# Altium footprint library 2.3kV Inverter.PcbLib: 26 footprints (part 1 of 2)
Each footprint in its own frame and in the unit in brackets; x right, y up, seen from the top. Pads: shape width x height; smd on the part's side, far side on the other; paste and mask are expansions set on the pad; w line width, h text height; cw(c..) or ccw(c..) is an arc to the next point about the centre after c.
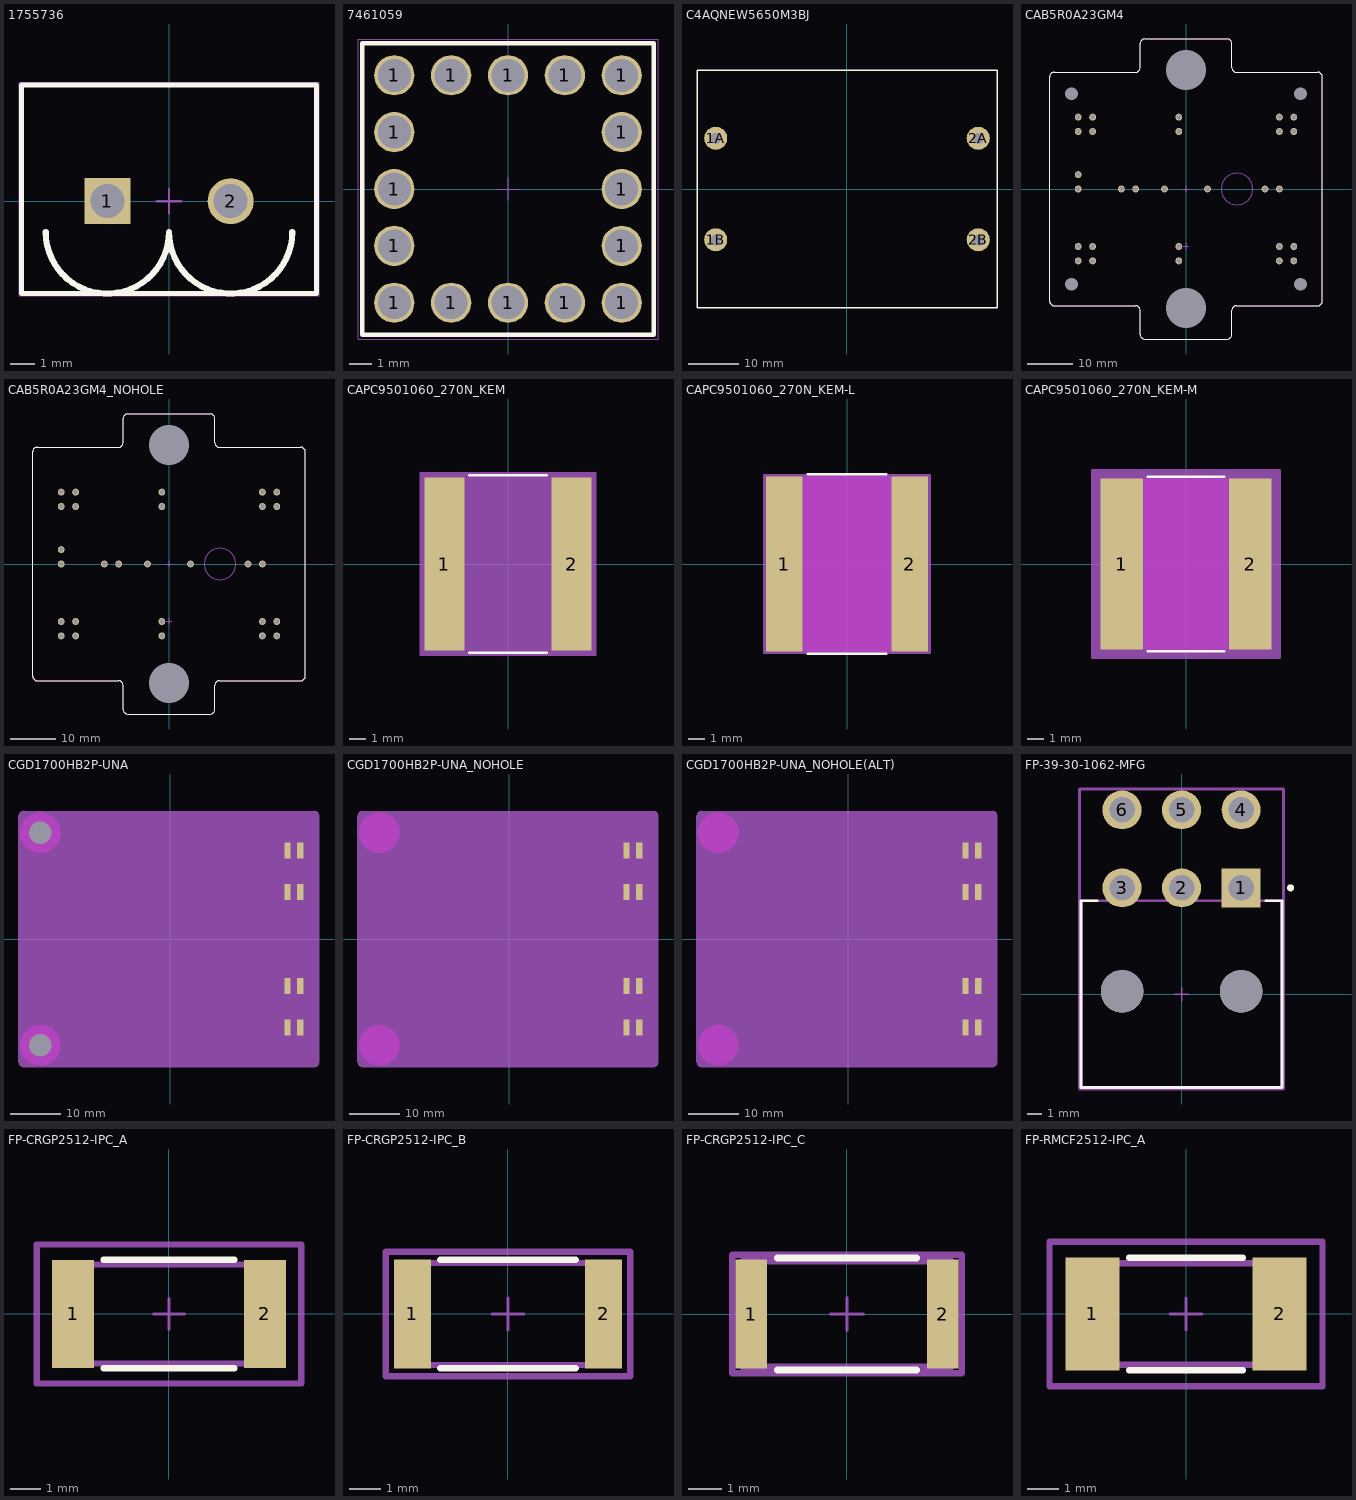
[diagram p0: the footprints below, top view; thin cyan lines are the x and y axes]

## 1755736 [mm] "THD, 2-Leads, Body 12.16x8.6mm, Pitch 5.08mm"
height 12
pads (2):
  rect 1.9x1.9 hole 1.4: 1(-2.54,0)
  round 1.9 hole 1.4: 2(2.54,0)
Top Overlay:
  lines w0.2: -6.08,-3.81 -6.08,4.79 6.08,4.79 6.08,-3.81 -6.08,-3.81
  lines w0.254: -5.08,-1.27 ccw(c-2.54,-1.27) 0,-1.27 ccw(c2.54,-1.27) 5.08,-1.27
Mechanical 13:
  lines w0.1: -6.08,-3.8 6.08,-3.8 6.08,4.8 -6.08,4.8 -6.08,-3.8
Mechanical 15:
  lines w0.05: -6.18,-3.9 -6.18,4.9 6.18,4.9 6.18,-3.9 -6.18,-3.9
  lines w0.1: -0.5,0 0.5,0 ; 0,-0.5 0,0.5
3D body: height 10, standoff -3.9, extent -3.04,-0.499 -2.044,0.499
3D body: height 10, standoff -3.9, extent 2.04,-0.499 3.036,0.499
3D body: height 12, standoff 4, extent -6.079,-3.799 6.079,4.799
3D body "Phoenix Contact 1755736.stp": height 12, standoff -3.9, extent -6,-3.7 6.16,4.87

## 7461059 [mm] "M6, thr 13.5mm"
height 13.5
pads (16):
  round 1.8 hole 1.475: 1(-5.08,-5.08) 1(-5.08,-2.54) 1(-5.08,0) 1(-5.08,2.54) 1(-5.08,5.08) 1(-2.54,-5.08) 1(-2.54,5.08) 1(0,-5.08) 1(0,5.08) 1(2.54,-5.08) 1(2.54,5.08) 1(5.08,-5.08) 1(5.08,-2.54) 1(5.08,0) 1(5.08,2.54) 1(5.08,5.08)
Top Overlay:
  lines w0.2: -6.5,-6.5 -6.5,6.5 6.5,6.5 6.5,-6.5 -6.5,-6.5
Top Courtyard:
  lines w0.05: -0.5,0 0.5,0 ; 0,-0.5 0,0.5 ; -6.7,-6.7 -6.7,6.7 6.7,6.7 6.7,-6.7 -6.7,-6.7
Top 3D Body:
  lines w0.1: -6.5,-6.5 -6.5,6.5 6.5,6.5 6.5,-6.5 -6.5,-6.5
Top Component Outline:
  lines w0.1: -6.5,-6.5 6.5,-6.5 6.5,6.5 -6.5,6.5 -6.5,-6.5
Top Designator:
  text ".Designator" at -7.498,-0.5 h1.5
3D body "7461059.STEP": height 13.5, standoff -3.5, extent -6.5,-6.5 6.5,6.5

## C4AQNEW5650M3BJ [mm]
pads (4):
  round 4.6 hole 2.2: 1A(-26.25,10.15) 1B(-26.25,-10.15) 2A(26.25,10.15) 2B(26.25,-10.15)
Top Overlay:
  lines w0.254: -30,-23.75 -30,23.75 30,23.75 30,-23.75 -30,-23.75
3D body "C4AQNEW5650M3BJ.step": height 65.3, standoff -6, extent -29.15,-22.805 29.15,22.7

## CAB5R0A23GM4 [mm] "Wolfpack GM Half-Bridge 2.3kV footprint"
pads (34):
  round 1.524 hole 1.1: AC_1(-24,-12.8) AC_2(-24,-16) AC_3(-20.8,-12.8) AC_4(-20.8,-16) AC_5(20.8,-12.8) AC_6(20.8,-16) AC_7(24,-12.8) AC_8(24,-16) DC+_1(-24,16) DC+_2(-24,12.8) DC+_3(-20.8,16) DC+_4(-20.8,12.8) DC+_5(20.8,16) DC+_6(20.8,12.8) DC+_7(24,16) DC+_8(24,12.8) DC-_1(20.8,0) DC-_2(17.6,0) DC-_3(-4.8,0) DC-_4(4.8,0) DC-_5(-11.2,0) DC-_6(-14.4,0) G1(-1.6,16) G2(-1.6,-16) S1(-1.6,12.8) S2(-1.6,-12.8) T1(-24,3.2) T2(-24,0)
  round 0.099 / inner round 1.524 / far side round 0.099 hole 2.794 unplated: ""(-25.5,-21.25) ""(-25.5,21.25) ""(25.5,-21.25) ""(25.5,21.25)
  round 0.1 hole 9 unplated: ""(0,-26.5) ""(0,26.5)
Top Overlay:
  lines w0.254: -30.35,-25 ccw(c-29.35,-25) -29.35,-26 -11.2,-26 cw(c-11.2,-27) -10.2,-27 -10.2,-32.4 ccw(c-9.2,-32.4) -9.2,-33.4 9.2,-33.4 ccw(c9.2,-32.4) 10.2,-32.4 10.2,-27 cw(c11.2,-27) 11.2,-26 29.35,-26 ccw(c29.35,-25) 30.35,-25 30.35,25 ccw(c29.35,25) 29.35,26 11.2,26 cw(c11.2,27) 10.2,27 10.2,32.4 ccw(c9.2,32.4) 9.2,33.4 -9.2,33.4 ccw(c-9.2,32.4) -10.2,32.4 -10.2,27 cw(c-11.2,27) -11.2,26 -29.35,26 ccw(c-29.35,25) -30.35,25 -30.35,-25
Mechanical 1:
  text "Hole size and tolerance need to checked before using this footprint" at 26,34.5 h1.52
  text "This footprint is mirrored. The footprint can be used on the bottom PCB side for module attach" at 23.5,-42.5 h1.52
Mechanical 5:
  text "G2" at 3.54,-16.46 h0.64
  text "AC_1" at -27.96,-13.248 h0.64
  text "T2" at 26.04,-0.46 h0.64
  text "T1" at 26.04,3.04 h0.64
  text "DC-_1" at -22.46,2.252 h0.64
  text "S1" at -0.96,12.54 h0.64
  text "T1" at -21.96,11.54 h0.64
  text "G1" at -0.96,15.54 h0.64
  text "DC+_1" at -28.46,15.752 h0.64
  text "T1" at -21.96,15.04 h0.64
  text "T2" at -21.96,12.04 h0.64
  text "DC+_2" at -28.46,12.452 h0.64
  text "DC+_3" at -18.96,15.752 h0.64
  text "DC+_4" at -18.96,12.452 h0.64
  text "DC+_5" at 16.04,15.752 h0.64
  text "DC+_6" at 16.04,12.452 h0.64
  text "DC+_7" at 26.04,15.752 h0.64
  text "DC+_8" at 26.04,12.452 h0.64
  text "DC-_2" at -18.96,2.252 h0.64
  text "DC-_3" at -6.46,2.252 h0.64
  text "DC-_4" at 3.54,2.252 h0.64
  text "DC-_5" at 9.54,2.252 h0.64
  text "DC-_6" at 13.04,2.252 h0.64
  text "S2" at 3.54,-13.16 h0.64
  text "AC_2" at -27.96,-16.248 h0.64
  text "AC_3" at -18.96,-13.248 h0.64
  text "AC_4" at -18.96,-16.248 h0.64
  text "AC_5" at 16.54,-13.248 h0.64
  text "AC_6" at 16.54,-16.248 h0.64
  text "AC_7" at 26.04,-13.248 h0.64
  text "AC_8" at 26.04,-16.248 h0.64
Mechanical 6:
  circle w0.25: c11.35,0 r3.5
  lines w0.254: -30.35,-25 ccw(c-29.35,-25) -29.35,-26 -11.2,-26 cw(c-11.2,-27) -10.2,-27 -10.2,-32.4 ccw(c-9.2,-32.4) -9.2,-33.4 9.2,-33.4 ccw(c9.2,-32.4) 10.2,-32.4 10.2,-27 cw(c11.2,-27) 11.2,-26 29.35,-26 ccw(c29.35,-25) 30.35,-25 30.35,25 ccw(c29.35,25) 29.35,26 11.2,26 cw(c11.2,27) 10.2,27 10.2,32.4 ccw(c9.2,32.4) 9.2,33.4 -9.2,33.4 ccw(c-9.2,32.4) -10.2,32.4 -10.2,27 cw(c-11.2,27) -11.2,26 -29.35,26 ccw(c-29.35,25) -30.35,25 -30.35,-25
Mechanical 8:
  lines w0.25: -0.67,-12.8 0.635,-12.8 ; -0.67,0 0.635,0 ; 0,-13.435 0,-12.13 ; 0,-0.635 0,0.67
3D body "CABxRxA23GM4.STEP": height 14.24, standoff -2.16, extent -28.346,-31.391 28.354,31.409

## CAB5R0A23GM4_NOHOLE [mm] "Wolfpack GM Half-Bridge 2.3kV footprint"
pads (30):
  round 1.524 hole 1.1: AC_1(-24,-12.8) AC_2(-24,-16) AC_3(-20.8,-12.8) AC_4(-20.8,-16) AC_5(20.8,-12.8) AC_6(20.8,-16) AC_7(24,-12.8) AC_8(24,-16) DC+_1(-24,16) DC+_2(-24,12.8) DC+_3(-20.8,16) DC+_4(-20.8,12.8) DC+_5(20.8,16) DC+_6(20.8,12.8) DC+_7(24,16) DC+_8(24,12.8) DC-_1(20.8,0) DC-_2(17.6,0) DC-_3(-4.8,0) DC-_4(4.8,0) DC-_5(-11.2,0) DC-_6(-14.4,0) G1(-1.6,16) G2(-1.6,-16) S1(-1.6,12.8) S2(-1.6,-12.8) T1(-24,3.2) T2(-24,0)
  round 0.1 hole 9 unplated: ""(0,-26.5) ""(0,26.5)
Top Overlay:
  lines w0.254: -30.35,-25 ccw(c-29.35,-25) -29.35,-26 -11.2,-26 cw(c-11.2,-27) -10.2,-27 -10.2,-32.4 ccw(c-9.2,-32.4) -9.2,-33.4 9.2,-33.4 ccw(c9.2,-32.4) 10.2,-32.4 10.2,-27 cw(c11.2,-27) 11.2,-26 29.35,-26 ccw(c29.35,-25) 30.35,-25 30.35,25 ccw(c29.35,25) 29.35,26 11.2,26 cw(c11.2,27) 10.2,27 10.2,32.4 ccw(c9.2,32.4) 9.2,33.4 -9.2,33.4 ccw(c-9.2,32.4) -10.2,32.4 -10.2,27 cw(c-11.2,27) -11.2,26 -29.35,26 ccw(c-29.35,25) -30.35,25 -30.35,-25
Mechanical 1:
  text "Hole size and tolerance need to checked before using this footprint" at 26,34.5 h1.52
  text "This footprint is mirrored. The footprint can be used on the bottom PCB side for module attach" at 23.5,-42.5 h1.52
Mechanical 5:
  text "G2" at 3.54,-16.46 h0.64
  text "AC_1" at -27.96,-13.248 h0.64
  text "T2" at 26.04,-0.46 h0.64
  text "T1" at 26.04,3.04 h0.64
  text "DC-_1" at -22.46,2.252 h0.64
  text "S1" at -0.96,12.54 h0.64
  text "T1" at -21.96,11.54 h0.64
  text "G1" at -0.96,15.54 h0.64
  text "DC+_1" at -28.46,15.752 h0.64
  text "T1" at -21.96,15.04 h0.64
  text "T2" at -21.96,12.04 h0.64
  text "DC+_2" at -28.46,12.452 h0.64
  text "DC+_3" at -18.96,15.752 h0.64
  text "DC+_4" at -18.96,12.452 h0.64
  text "DC+_5" at 16.04,15.752 h0.64
  text "DC+_6" at 16.04,12.452 h0.64
  text "DC+_7" at 26.04,15.752 h0.64
  text "DC+_8" at 26.04,12.452 h0.64
  text "DC-_2" at -18.96,2.252 h0.64
  text "DC-_3" at -6.46,2.252 h0.64
  text "DC-_4" at 3.54,2.252 h0.64
  text "DC-_5" at 9.54,2.252 h0.64
  text "DC-_6" at 13.04,2.252 h0.64
  text "S2" at 3.54,-13.16 h0.64
  text "AC_2" at -27.96,-16.248 h0.64
  text "AC_3" at -18.96,-13.248 h0.64
  text "AC_4" at -18.96,-16.248 h0.64
  text "AC_5" at 16.54,-13.248 h0.64
  text "AC_6" at 16.54,-16.248 h0.64
  text "AC_7" at 26.04,-13.248 h0.64
  text "AC_8" at 26.04,-16.248 h0.64
Mechanical 6:
  circle w0.25: c11.35,0 r3.5
  lines w0.254: -30.35,-25 ccw(c-29.35,-25) -29.35,-26 -11.2,-26 cw(c-11.2,-27) -10.2,-27 -10.2,-32.4 ccw(c-9.2,-32.4) -9.2,-33.4 9.2,-33.4 ccw(c9.2,-32.4) 10.2,-32.4 10.2,-27 cw(c11.2,-27) 11.2,-26 29.35,-26 ccw(c29.35,-25) 30.35,-25 30.35,25 ccw(c29.35,25) 29.35,26 11.2,26 cw(c11.2,27) 10.2,27 10.2,32.4 ccw(c9.2,32.4) 9.2,33.4 -9.2,33.4 ccw(c-9.2,32.4) -10.2,32.4 -10.2,27 cw(c-11.2,27) -11.2,26 -29.35,26 ccw(c-29.35,25) -30.35,25 -30.35,-25
Mechanical 8:
  lines w0.25: -0.67,-12.8 0.635,-12.8 ; -0.67,0 0.635,0 ; 0,-13.435 0,-12.13 ; 0,-0.635 0,0.67
3D body "93070A095_Alloy Steel Low-Profile Socket Head Screw.STEP": height 17.35, standoff 8.55, extent -3.488,23 3.488,30
3D body "93070A095_Alloy Steel Low-Profile Socket Head Screw.STEP": height 17.35, standoff 8.55, extent -3.488,-30 3.488,-23
3D body "CABxRxA23GM4.STEP": height 14.24, standoff -2.16, extent -28.346,-31.391 28.354,31.409

## CAPC9501060_270N_KEM [mm]
pads (2):
  rect 2.426x10.6 smd paste+0 mask+0: 1(-3.893,0) 2(3.893,0)
Top Overlay:
  lines w0.152: -2.372,-5.427 2.372,-5.427 ; -2.372,5.427 2.372,5.427
Top Solder:
  rectangle: -2.73,-5.524 2.73,5.524
Mechanical 13:
  lines w0.025: -4.75,-5.3 -4.75,5.3 ; -4.75,-5.3 4.75,-5.3 ; -4.75,-5.3 -3.08,-5.3 -3.08,5.3 -4.75,5.3 ; -4.75,-5.3 -4.75,5.3 ; -4.75,5.3 4.75,5.3 ; 4.75,-5.3 4.75,5.3 ; 4.75,-5.3 4.75,5.3 ; 4.75,-5.3 3.08,-5.3 3.08,5.3 4.75,5.3
Mechanical 15:
  region: 5.36,-5.554 -5.36,-5.554 -5.36,5.554 5.36,5.554
  lines w0.152: -5.36,-5.554 5.36,-5.554 5.36,5.554 -5.36,5.554 -5.36,-5.554
3D body "CAPC9501060_270N_KEM.step": height 2.7, standoff 0, extent -4.75,-5.3 4.75,5.3

## CAPC9501060_270N_KEM-L [mm]
pads (2):
  rect 2.222x10.549 smd paste+0 mask+0: 1(-3.791,0) 2(3.791,0)
Top Layer keep-out:
  region: -2.629,-5.249 -2.629,5.249 2.629,5.249 2.629,-5.249
Top Overlay:
  lines w0.152: -2.384,-5.427 2.384,-5.427 ; -2.384,5.427 2.384,5.427
Keep-Out Layer:
  region: -2.629,-5.3 -2.629,5.3 2.629,5.3 2.629,-5.3
Mechanical 13:
  lines w0.025: -4.75,-5.3 -4.75,5.3 ; -4.75,-5.3 4.75,-5.3 ; -4.75,-5.3 -3.08,-5.3 -3.08,5.3 -4.75,5.3 ; -4.75,-5.3 -4.75,5.3 ; -4.75,5.3 4.75,5.3 ; 4.75,-5.3 4.75,5.3 ; 4.75,-5.3 4.75,5.3 ; 4.75,-5.3 3.08,-5.3 3.08,5.3 4.75,5.3
Mechanical 15:
  region: 5.004,-5.376 -5.004,-5.376 -5.004,5.376 5.004,5.376
  lines w0.152: -5.004,-5.376 5.004,-5.376 5.004,5.376 -5.004,5.376 -5.004,-5.376
3D body "CAPC9501060_270N_KEM.step": height 2.7, standoff 0, extent -4.75,-5.3 4.75,5.3

## CAPC9501060_270N_KEM-M [mm]
pads (2):
  rect 2.629x10.651 smd paste+0 mask+0: 1(-3.994,0) 2(3.994,0)
Top Layer keep-out:
  region: -2.629,-5.249 -2.629,5.249 2.629,5.249 2.629,-5.249
Top Overlay:
  lines w0.152: -2.363,-5.427 2.363,-5.427 ; -2.363,5.427 2.363,5.427
Keep-Out Layer:
  region: -2.629,-5.3 -2.629,5.3 2.629,5.3 2.629,-5.3
Mechanical 13:
  lines w0.025: -4.75,-5.3 -4.75,5.3 ; -4.75,-5.3 4.75,-5.3 ; -4.75,-5.3 -3.08,-5.3 -3.08,5.3 -4.75,5.3 ; -4.75,-5.3 -4.75,5.3 ; -4.75,5.3 4.75,5.3 ; 4.75,-5.3 4.75,5.3 ; 4.75,-5.3 4.75,5.3 ; 4.75,-5.3 3.08,-5.3 3.08,5.3 4.75,5.3
Mechanical 15:
  region: 5.817,-5.833 -5.817,-5.833 -5.817,5.833 5.817,5.833
  lines w0.152: -5.817,-5.833 5.817,-5.833 5.817,5.833 -5.817,5.833 -5.817,-5.833
3D body "CAPC9501060_270N_KEM.step": height 2.7, standoff 0, extent -4.75,-5.3 4.75,5.3

## CGD1700HB2P-UNA [mil] "Wolfpack FM/GM Gate Driver"
pads (10):
  rect 50x125 smd: 1A(917.84,369) 1B(917.84,-694) 2A(917.84,694) 2B(917.84,-369) 3A(1017.84,369) 3B(1017.84,-694) 4A(1017.84,694) 4B(1017.84,-369)
  round 20 hole 175 unplated: ""(-1017.84,-832.52) ""(-1017.84,832.52)
Top Courtyard:
  dashed: 1164.68,-965 1164.68,965 1164.55,968.05 1164.15,971.08 1163.49,974.06 1162.57,976.97 1161.41,979.79 1160,982.5 1158.36,985.08 1156.5,987.5 1154.43,989.75 1152.18,991.81 1149.76,993.67 1147.18,995.31 1144.48,996.72 1141.66,997.89 1138.74,998.81 1135.76,999.47 1132.74,999.87 1129.68,1000 -1150.32,1000 -1153.37,999.87 -1156.39,999.47 -1159.37,998.81 -1162.29,997.89 -1165.11,996.72 -1167.82,995.31 -1170.39,993.67 -1172.81,991.81 -1175.06,989.75 -1177.13,987.5 -1178.99,985.08 -1180.63,982.5 -1182.04,979.79 -1183.2,976.97 -1184.12,974.06 -1184.78,971.08 -1185.18,968.05 -1185.32,965 -1185.32,-965 -1185.18,-968.05 -1184.78,-971.08 -1184.12,-974.06 -1183.2,-976.97 -1182.04,-979.79 -1180.63,-982.5 -1178.99,-985.08 -1177.13,-987.5 -1175.06,-989.75 -1172.81,-991.81 -1170.39,-993.67 -1167.82,-995.31 -1165.11,-996.72 -1162.29,-997.89 -1159.37,-998.81 -1156.39,-999.47 -1153.37,-999.87 -1150.32,-1000 1129.68,-1000 1132.74,-999.87 1135.76,-999.47 1138.74,-998.81 1141.66,-997.89 1144.48,-996.72 1147.18,-995.31 1149.76,-993.67 1152.18,-991.81 1154.43,-989.75 1156.5,-987.5 1158.36,-985.08 1160,-982.5 1161.41,-979.79 1162.57,-976.97 1163.49,-974.06 1164.15,-971.08 1164.55,-968.05
Top 3D Body:
  region: 1164.68,-965 1164.68,965 1164.55,968.05 1164.15,971.08 1163.49,974.06 1162.57,976.97 1161.41,979.79 1160,982.5 1158.36,985.08 1156.5,987.5 1154.43,989.75 1152.18,991.81 1149.76,993.67 1147.18,995.31 1144.48,996.72 1141.66,997.89 1138.74,998.81 1135.76,999.47 1132.74,999.87 1129.68,1000 -1150.32,1000 -1153.37,999.87 -1156.39,999.47 -1159.37,998.81 -1162.29,997.89 -1165.11,996.72 -1167.82,995.31 -1170.39,993.67 -1172.81,991.81 -1175.06,989.75 -1177.13,987.5 -1178.99,985.08 -1180.63,982.5 -1182.04,979.79 -1183.2,976.97 -1184.12,974.06 -1184.78,971.08 -1185.18,968.05 -1185.32,965 -1185.32,-965 -1185.18,-968.05 -1184.78,-971.08 -1184.12,-974.06 -1183.2,-976.97 -1182.04,-979.79 -1180.63,-982.5 -1178.99,-985.08 -1177.13,-987.5 -1175.06,-989.75 -1172.81,-991.81 -1170.39,-993.67 -1167.82,-995.31 -1165.11,-996.72 -1162.29,-997.89 -1159.37,-998.81 -1156.39,-999.47 -1153.37,-999.87 -1150.32,-1000 1129.68,-1000 1132.74,-999.87 1135.76,-999.47 1138.74,-998.81 1141.66,-997.89 1144.48,-996.72 1147.18,-995.31 1149.76,-993.67 1152.18,-991.81 1154.43,-989.75 1156.5,-987.5 1158.36,-985.08 1160,-982.5 1161.41,-979.79 1162.57,-976.97 1163.49,-974.06 1164.15,-971.08 1164.55,-968.05
Mechanical 12:
  lines w1: 867.84,-631.5 867.84,-431.5 1067.84,-431.5 1067.84,-631.5 867.84,-631.5 ; 867.84,431.5 867.84,631.5 1067.84,631.5 1067.84,431.5 867.84,431.5 ; 917.83,-611.5 cw(c917.83,-581.5) 917.83,-551.49 cw(c917.83,-581.5) 917.83,-611.5 ; 917.83,-511.5 cw(c917.83,-481.5) 917.83,-451.49 cw(c917.83,-481.5) 917.83,-511.5 ; 917.83,451.49 cw(c917.83,481.5) 917.83,511.5 cw(c917.83,481.5) 917.83,451.49 ; 917.83,551.49 cw(c917.83,581.5) 917.83,611.5 cw(c917.83,581.5) 917.83,551.49 ; 1017.83,-611.5 cw(c1017.83,-581.5) 1017.83,-551.49 cw(c1017.83,-581.5) 1017.83,-611.5 ; 1017.83,-511.5 cw(c1017.83,-481.5) 1017.83,-451.49 cw(c1017.83,-481.5) 1017.83,-511.5 ; 1017.83,451.49 cw(c1017.83,481.5) 1017.83,511.5 cw(c1017.83,481.5) 1017.83,451.49 ; 1017.83,551.49 cw(c1017.83,581.5) 1017.83,611.5 cw(c1017.83,581.5) 1017.83,551.49
Mechanical 13:
  lines w1: 892.84,-619 1042.84,-619 1042.84,-444 892.84,-444 892.84,-619 ; 892.84,444 1042.84,444 1042.84,619 892.84,619 892.84,444
Mechanical 15:
  text "4" at 997.84,-744 h25
  text "42" at 877.84,-744 h25
  text "2" at 997.84,319 h25
  text "22" at 877.84,319 h25
  text "3" at 997.84,-419 h25
  text "32" at 877.84,-419 h25
  text "1" at 997.84,644 h25
  text "12" at 877.84,644 h25
Top Assembly:
  circle w1: c-1017.84,832.52 r87.5
  circle w1: c-1017.84,-832.52 r87.5
  lines w1: -1185.32,-965 ccw(c-1150.32,-965) -1150.32,-1000 1129.68,-1000 ccw(c1129.68,-965) 1164.68,-965 1164.68,965 ccw(c1129.68,965) 1129.68,1000 -1150.32,1000 ccw(c-1150.32,965) -1185.32,965 -1185.32,-965 ; -1175.32,-550 -815.32,-550 -815.32,550 -1175.32,550 -1175.32,-550 ; -1175.32,-95 -1135.32,-95 -1135.32,95 -1175.32,95 -1175.32,-95 ; -1045.32,-370 cw(c-1045.32,-350) -1045.32,-330 cw(c-1045.32,-350) -1045.32,-370 ; -1045.32,-270 cw(c-1045.32,-250) -1045.32,-230 cw(c-1045.32,-250) -1045.32,-270 ; -1045.32,-170 cw(c-1045.32,-150) -1045.32,-130 cw(c-1045.32,-150) -1045.32,-170 ; -1045.32,-70 cw(c-1045.32,-50) -1045.32,-30 cw(c-1045.32,-50) -1045.32,-70 ; -1045.32,30 cw(c-1045.32,50) -1045.32,70 cw(c-1045.32,50) -1045.32,30 ; -1045.32,130 cw(c-1045.32,150) -1045.32,170 cw(c-1045.32,150) -1045.32,130 ; -1045.32,230 cw(c-1045.32,250) -1045.32,270 cw(c-1045.32,250) -1045.32,230 ; -1045.32,330 cw(c-1045.32,350) -1045.32,370 cw(c-1045.32,350) -1045.32,330 ; -945.32,-370 cw(c-945.32,-350) -945.32,-330 cw(c-945.32,-350) -945.32,-370 ; -945.32,-270 cw(c-945.32,-250) -945.32,-230 cw(c-945.32,-250) -945.32,-270 ; -945.32,-170 cw(c-945.32,-150) -945.32,-130 cw(c-945.32,-150) -945.32,-170 ; -945.32,-70 cw(c-945.32,-50) -945.32,-30 cw(c-945.32,-50) -945.32,-70 ; -945.32,30 cw(c-945.32,50) -945.32,70 cw(c-945.32,50) -945.32,30 ; -945.32,130 cw(c-945.32,150) -945.32,170 cw(c-945.32,150) -945.32,130 ; -945.32,230 cw(c-945.32,250) -945.32,270 cw(c-945.32,250) -945.32,230 ; -945.32,330 cw(c-945.32,350) -945.32,370 cw(c-945.32,350) -945.32,330 ; 867.84,-631.5 1067.84,-631.5 1067.84,-431.5 867.84,-431.5 867.84,-631.5 ; 867.84,431.5 1067.84,431.5 1067.84,631.5 867.84,631.5 867.84,431.5
  text "HS" at 1155.18,470.79 h75
  text "LS" at 1155.18,-589.21 h75
  text "S" at 1002.18,247 h75
  text "G" at 1002.18,772 h75
  text "G" at 1002.18,-303 h75
  text "S" at 1002.18,-828 h75
Multi-Layer keep-out:
  region: -1017.84,-675.04 -1031.56,-675.64 -1045.18,-677.43 -1058.59,-680.41 -1071.7,-684.54 -1084.39,-689.79 -1096.58,-696.14 -1108.16,-703.52 -1119.06,-711.88 -1129.19,-721.16 -1138.47,-731.29 -1146.84,-742.19 -1154.22,-753.78 -1160.56,-765.97 -1165.82,-778.66 -1169.95,-791.76 -1172.92,-805.17 -1174.72,-818.79 -1175.32,-832.52 -1174.72,-846.25 -1172.92,-859.87 -1169.95,-873.28 -1165.82,-886.38 -1160.56,-899.07 -1154.22,-911.26 -1146.84,-922.85 -1138.47,-933.75 -1129.19,-943.88 -1119.06,-953.16 -1108.16,-961.52 -1096.58,-968.9 -1084.39,-975.25 -1071.7,-980.5 -1058.59,-984.63 -1045.18,-987.61 -1031.56,-989.4 -1017.84,-990 -1004.11,-989.4 -990.49,-987.61 -977.08,-984.63 -963.97,-980.5 -951.28,-975.25 -939.1,-968.9 -927.51,-961.52 -916.61,-953.16 -906.48,-943.88 -897.2,-933.75 -888.83,-922.85 -881.45,-911.26 -875.11,-899.07 -869.85,-886.38 -865.72,-873.28 -862.75,-859.87 -860.95,-846.25 -860.36,-832.52 -860.95,-818.79 -862.75,-805.17 -865.72,-791.76 -869.85,-778.66 -875.11,-765.97 -881.45,-753.78 -888.83,-742.19 -897.2,-731.29 -906.48,-721.16 -916.61,-711.88 -927.51,-703.52 -939.1,-696.14 -951.28,-689.79 -963.97,-684.54 -977.08,-680.41 -990.49,-677.43 -1004.11,-675.64
  region: -1017.84,990 -1031.56,989.4 -1045.18,987.61 -1058.59,984.63 -1071.7,980.5 -1084.39,975.25 -1096.58,968.9 -1108.16,961.52 -1119.06,953.16 -1129.19,943.88 -1138.47,933.75 -1146.84,922.85 -1154.22,911.26 -1160.56,899.07 -1165.82,886.38 -1169.95,873.28 -1172.92,859.87 -1174.72,846.25 -1175.32,832.52 -1174.72,818.79 -1172.92,805.17 -1169.95,791.76 -1165.82,778.66 -1160.56,765.97 -1154.22,753.78 -1146.84,742.19 -1138.47,731.29 -1129.19,721.16 -1119.06,711.88 -1108.16,703.52 -1096.58,696.14 -1084.39,689.79 -1071.7,684.54 -1058.59,680.41 -1045.18,677.43 -1031.56,675.64 -1017.84,675.04 -1004.11,675.64 -990.49,677.43 -977.08,680.41 -963.97,684.54 -951.28,689.79 -939.1,696.14 -927.51,703.52 -916.61,711.88 -906.48,721.16 -897.2,731.29 -888.83,742.19 -881.45,753.78 -875.11,765.97 -869.85,778.66 -865.72,791.76 -862.75,805.17 -860.95,818.79 -860.36,832.52 -860.95,846.25 -862.75,859.87 -865.72,873.28 -869.85,886.38 -875.11,899.07 -881.45,911.26 -888.83,922.85 -897.2,933.75 -906.48,943.88 -916.61,953.16 -927.51,961.52 -939.1,968.9 -951.28,975.25 -963.97,980.5 -977.08,984.63 -990.49,987.61 -1004.11,989.4
Mechanical 17:
  lines w1: -1185.32,-965 ccw(c-1150.32,-965) -1150.32,-1000 1129.68,-1000 ccw(c1129.68,-965) 1164.68,-965 1164.68,965 ccw(c1129.68,965) 1129.68,1000 -1150.32,1000 ccw(c-1150.32,965) -1185.32,965 -1185.32,-965
3D body "CGD1700HB2M-UNA STEP.STEP": height 1020.55, standoff 158.13, extent -1185,-1237 1165,1000
3D body "TSM-102-01-SM-DV.step": height 390, standoff 0, extent 870,-681.5 1070,-378.5
3D body "TSM-102-01-SM-DV.step": height 390, standoff 0, extent 865,378.5 1065,681.5
3D body "95783A015_Nylon 6-6 Male-Female Threaded Hex Standoff.STEP": height 846.46, standoff 0, extent -1135.95,-965.19 -899.72,-699.85
3D body "95783A015_Nylon 6-6 Male-Female Threaded Hex Standoff.STEP": height 846.46, standoff 0, extent -1135.95,699.85 -899.72,965.19

## CGD1700HB2P-UNA_NOHOLE [mil] "Wolfpack FM/GM Gate Driver"
pads (8):
  rect 50x125 smd: 1A(917.84,369) 1B(917.84,-694) 2A(917.84,694) 2B(917.84,-369) 3A(1017.84,369) 3B(1017.84,-694) 4A(1017.84,694) 4B(1017.84,-369)
Top Courtyard:
  dashed: 1164.68,-965 1164.68,965 1164.55,968.05 1164.15,971.08 1163.49,974.06 1162.57,976.97 1161.41,979.79 1160,982.5 1158.36,985.08 1156.5,987.5 1154.43,989.75 1152.18,991.81 1149.76,993.67 1147.18,995.31 1144.48,996.72 1141.66,997.89 1138.74,998.81 1135.76,999.47 1132.74,999.87 1129.68,1000 -1150.32,1000 -1153.37,999.87 -1156.39,999.47 -1159.37,998.81 -1162.29,997.89 -1165.11,996.72 -1167.82,995.31 -1170.39,993.67 -1172.81,991.81 -1175.06,989.75 -1177.13,987.5 -1178.99,985.08 -1180.63,982.5 -1182.04,979.79 -1183.2,976.97 -1184.12,974.06 -1184.78,971.08 -1185.18,968.05 -1185.32,965 -1185.32,-965 -1185.18,-968.05 -1184.78,-971.08 -1184.12,-974.06 -1183.2,-976.97 -1182.04,-979.79 -1180.63,-982.5 -1178.99,-985.08 -1177.13,-987.5 -1175.06,-989.75 -1172.81,-991.81 -1170.39,-993.67 -1167.82,-995.31 -1165.11,-996.72 -1162.29,-997.89 -1159.37,-998.81 -1156.39,-999.47 -1153.37,-999.87 -1150.32,-1000 1129.68,-1000 1132.74,-999.87 1135.76,-999.47 1138.74,-998.81 1141.66,-997.89 1144.48,-996.72 1147.18,-995.31 1149.76,-993.67 1152.18,-991.81 1154.43,-989.75 1156.5,-987.5 1158.36,-985.08 1160,-982.5 1161.41,-979.79 1162.57,-976.97 1163.49,-974.06 1164.15,-971.08 1164.55,-968.05
Top 3D Body:
  region: 1164.68,-965 1164.68,965 1164.55,968.05 1164.15,971.08 1163.49,974.06 1162.57,976.97 1161.41,979.79 1160,982.5 1158.36,985.08 1156.5,987.5 1154.43,989.75 1152.18,991.81 1149.76,993.67 1147.18,995.31 1144.48,996.72 1141.66,997.89 1138.74,998.81 1135.76,999.47 1132.74,999.87 1129.68,1000 -1150.32,1000 -1153.37,999.87 -1156.39,999.47 -1159.37,998.81 -1162.29,997.89 -1165.11,996.72 -1167.82,995.31 -1170.39,993.67 -1172.81,991.81 -1175.06,989.75 -1177.13,987.5 -1178.99,985.08 -1180.63,982.5 -1182.04,979.79 -1183.2,976.97 -1184.12,974.06 -1184.78,971.08 -1185.18,968.05 -1185.32,965 -1185.32,-965 -1185.18,-968.05 -1184.78,-971.08 -1184.12,-974.06 -1183.2,-976.97 -1182.04,-979.79 -1180.63,-982.5 -1178.99,-985.08 -1177.13,-987.5 -1175.06,-989.75 -1172.81,-991.81 -1170.39,-993.67 -1167.82,-995.31 -1165.11,-996.72 -1162.29,-997.89 -1159.37,-998.81 -1156.39,-999.47 -1153.37,-999.87 -1150.32,-1000 1129.68,-1000 1132.74,-999.87 1135.76,-999.47 1138.74,-998.81 1141.66,-997.89 1144.48,-996.72 1147.18,-995.31 1149.76,-993.67 1152.18,-991.81 1154.43,-989.75 1156.5,-987.5 1158.36,-985.08 1160,-982.5 1161.41,-979.79 1162.57,-976.97 1163.49,-974.06 1164.15,-971.08 1164.55,-968.05
Mechanical 12:
  lines w1: 867.84,-631.5 1067.84,-631.5 1067.84,-431.5 867.84,-431.5 867.84,-631.5 ; 867.84,431.5 1067.84,431.5 1067.84,631.5 867.84,631.5 867.84,431.5 ; 917.83,-611.5 ccw(c917.83,-581.5) 917.83,-551.49 ccw(c917.83,-581.5) 917.83,-611.5 ; 917.83,-511.5 ccw(c917.83,-481.5) 917.83,-451.49 ccw(c917.83,-481.5) 917.83,-511.5 ; 917.83,451.49 ccw(c917.83,481.5) 917.83,511.5 ccw(c917.83,481.5) 917.83,451.49 ; 917.83,551.49 ccw(c917.83,581.5) 917.83,611.5 ccw(c917.83,581.5) 917.83,551.49 ; 1017.83,-611.5 ccw(c1017.83,-581.5) 1017.83,-551.49 ccw(c1017.83,-581.5) 1017.83,-611.5 ; 1017.83,-511.5 ccw(c1017.83,-481.5) 1017.83,-451.49 ccw(c1017.83,-481.5) 1017.83,-511.5 ; 1017.83,451.49 ccw(c1017.83,481.5) 1017.83,511.5 ccw(c1017.83,481.5) 1017.83,451.49 ; 1017.83,551.49 ccw(c1017.83,581.5) 1017.83,611.5 ccw(c1017.83,581.5) 1017.83,551.49
Mechanical 13:
  lines w1: 892.84,-619 892.84,-444 1042.84,-444 1042.84,-619 892.84,-619 ; 892.84,444 892.84,619 1042.84,619 1042.84,444 892.84,444
Mechanical 15:
  text "12" at 877.84,644 h25
  text "1" at 997.84,644 h25
  text "32" at 877.84,-419 h25
  text "3" at 997.84,-419 h25
  text "22" at 877.84,319 h25
  text "2" at 997.84,319 h25
  text "42" at 877.84,-744 h25
  text "4" at 997.84,-744 h25
Top Assembly:
  circle w1: c-1017.84,-832.52 r87.5
  circle w1: c-1017.84,832.52 r87.5
  lines w1: -1185.32,-965 ccw(c-1150.32,-965) -1150.32,-1000 1129.68,-1000 ccw(c1129.68,-965) 1164.68,-965 1164.68,965 ccw(c1129.68,965) 1129.68,1000 -1150.32,1000 ccw(c-1150.32,965) -1185.32,965 -1185.32,-965 ; -1175.32,-550 -1175.32,550 -815.32,550 -815.32,-550 -1175.32,-550 ; -1175.32,-95 -1175.32,95 -1135.32,95 -1135.32,-95 -1175.32,-95 ; -1045.32,-370 ccw(c-1045.32,-350) -1045.32,-330 ccw(c-1045.32,-350) -1045.32,-370 ; -1045.32,-270 ccw(c-1045.32,-250) -1045.32,-230 ccw(c-1045.32,-250) -1045.32,-270 ; -1045.32,-170 ccw(c-1045.32,-150) -1045.32,-130 ccw(c-1045.32,-150) -1045.32,-170 ; -1045.32,-70 ccw(c-1045.32,-50) -1045.32,-30 ccw(c-1045.32,-50) -1045.32,-70 ; -1045.32,30 ccw(c-1045.32,50) -1045.32,70 ccw(c-1045.32,50) -1045.32,30 ; -1045.32,130 ccw(c-1045.32,150) -1045.32,170 ccw(c-1045.32,150) -1045.32,130 ; -1045.32,230 ccw(c-1045.32,250) -1045.32,270 ccw(c-1045.32,250) -1045.32,230 ; -1045.32,330 ccw(c-1045.32,350) -1045.32,370 ccw(c-1045.32,350) -1045.32,330 ; -945.32,-370 ccw(c-945.32,-350) -945.32,-330 ccw(c-945.32,-350) -945.32,-370 ; -945.32,-270 ccw(c-945.32,-250) -945.32,-230 ccw(c-945.32,-250) -945.32,-270 ; -945.32,-170 ccw(c-945.32,-150) -945.32,-130 ccw(c-945.32,-150) -945.32,-170 ; -945.32,-70 ccw(c-945.32,-50) -945.32,-30 ccw(c-945.32,-50) -945.32,-70 ; -945.32,30 ccw(c-945.32,50) -945.32,70 ccw(c-945.32,50) -945.32,30 ; -945.32,130 ccw(c-945.32,150) -945.32,170 ccw(c-945.32,150) -945.32,130 ; -945.32,230 ccw(c-945.32,250) -945.32,270 ccw(c-945.32,250) -945.32,230 ; -945.32,330 ccw(c-945.32,350) -945.32,370 ccw(c-945.32,350) -945.32,330 ; 867.84,-631.5 867.84,-431.5 1067.84,-431.5 1067.84,-631.5 867.84,-631.5 ; 867.84,431.5 867.84,631.5 1067.84,631.5 1067.84,431.5 867.84,431.5
  text "S" at 1002.18,-828 h75
  text "G" at 1002.18,-303 h75
  text "G" at 1002.18,772 h75
  text "S" at 1002.18,247 h75
  text "LS" at 1155.18,-589.21 h75
  text "HS" at 1155.18,470.79 h75
Multi-Layer keep-out:
  region: -1017.84,990 -1031.56,989.4 -1045.18,987.61 -1058.59,984.63 -1071.7,980.5 -1084.39,975.25 -1096.58,968.9 -1108.16,961.52 -1119.06,953.16 -1129.19,943.88 -1138.47,933.75 -1146.84,922.85 -1154.22,911.26 -1160.56,899.07 -1165.82,886.38 -1169.95,873.28 -1172.92,859.87 -1174.72,846.25 -1175.32,832.52 -1174.72,818.79 -1172.92,805.17 -1169.95,791.76 -1165.82,778.66 -1160.56,765.97 -1154.22,753.78 -1146.84,742.19 -1138.47,731.29 -1129.19,721.16 -1119.06,711.88 -1108.16,703.52 -1096.58,696.14 -1084.39,689.79 -1071.7,684.54 -1058.59,680.41 -1045.18,677.43 -1031.56,675.64 -1017.84,675.04 -1004.11,675.64 -990.49,677.43 -977.08,680.41 -963.97,684.54 -951.28,689.79 -939.1,696.14 -927.51,703.52 -916.61,711.88 -906.48,721.16 -897.2,731.29 -888.83,742.19 -881.45,753.78 -875.11,765.97 -869.85,778.66 -865.72,791.76 -862.75,805.17 -860.95,818.79 -860.36,832.52 -860.95,846.25 -862.75,859.87 -865.72,873.28 -869.85,886.38 -875.11,899.07 -881.45,911.26 -888.83,922.85 -897.2,933.75 -906.48,943.88 -916.61,953.16 -927.51,961.52 -939.1,968.9 -951.28,975.25 -963.97,980.5 -977.08,984.63 -990.49,987.61 -1004.11,989.4
  region: -1017.84,-675.04 -1031.56,-675.64 -1045.18,-677.43 -1058.59,-680.41 -1071.7,-684.54 -1084.39,-689.79 -1096.58,-696.14 -1108.16,-703.52 -1119.06,-711.88 -1129.19,-721.16 -1138.47,-731.29 -1146.84,-742.19 -1154.22,-753.78 -1160.56,-765.97 -1165.82,-778.66 -1169.95,-791.76 -1172.92,-805.17 -1174.72,-818.79 -1175.32,-832.52 -1174.72,-846.25 -1172.92,-859.87 -1169.95,-873.28 -1165.82,-886.38 -1160.56,-899.07 -1154.22,-911.26 -1146.84,-922.85 -1138.47,-933.75 -1129.19,-943.88 -1119.06,-953.16 -1108.16,-961.52 -1096.58,-968.9 -1084.39,-975.25 -1071.7,-980.5 -1058.59,-984.63 -1045.18,-987.61 -1031.56,-989.4 -1017.84,-990 -1004.11,-989.4 -990.49,-987.61 -977.08,-984.63 -963.97,-980.5 -951.28,-975.25 -939.1,-968.9 -927.51,-961.52 -916.61,-953.16 -906.48,-943.88 -897.2,-933.75 -888.83,-922.85 -881.45,-911.26 -875.11,-899.07 -869.85,-886.38 -865.72,-873.28 -862.75,-859.87 -860.95,-846.25 -860.36,-832.52 -860.95,-818.79 -862.75,-805.17 -865.72,-791.76 -869.85,-778.66 -875.11,-765.97 -881.45,-753.78 -888.83,-742.19 -897.2,-731.29 -906.48,-721.16 -916.61,-711.88 -927.51,-703.52 -939.1,-696.14 -951.28,-689.79 -963.97,-684.54 -977.08,-680.41 -990.49,-677.43 -1004.11,-675.64
Mechanical 17:
  lines w1: -1185.32,-965 ccw(c-1150.32,-965) -1150.32,-1000 1129.68,-1000 ccw(c1129.68,-965) 1164.68,-965 1164.68,965 ccw(c1129.68,965) 1129.68,1000 -1150.32,1000 ccw(c-1150.32,965) -1185.32,965 -1185.32,-965
3D body "TSM-102-01-SM-DV.step": height 390, standoff 0, extent 865,378.5 1065,681.5
3D body "TSM-102-01-SM-DV.step": height 390, standoff 0, extent 870,-681.5 1070,-378.5
3D body "M4_07MM - Single.STEP": height 966.14, standoff 375.59, extent -1199.68,-990 -835.99,-675.04
3D body "M4_07MM - Single.STEP": height 966.14, standoff 375.59, extent -1199.68,675.04 -835.99,990
3D body "M4_07MM - Single.STEP": height 966.14, standoff 375.59, extent 815.68,-157.48 1179.36,157.48
3D body "93369A127_Nylon Hex Nut.STEP": height 822.05, standoff 688.94, extent -1153.66,675.68 -882.01,989.36
3D body "93369A127_Nylon Hex Nut.STEP": height 822.05, standoff 688.94, extent -1153.66,-989.36 -882.01,-675.68
3D body "93369A127_Nylon Hex Nut.STEP": height 822.05, standoff 688.94, extent 861.69,-156.84 1133.35,156.84
3D body "92492A216_Nylon Pan Head Phillips Screws.STEP": height 509.81, standoff 151.54, extent -1175.32,675.04 -860.35,990
3D body "92492A216_Nylon Pan Head Phillips Screws.STEP": height 509.81, standoff 151.54, extent -1175.32,-990 -860.35,-675.04
3D body "92492A216_Nylon Pan Head Phillips Screws.STEP": height 509.81, standoff 151.54, extent 840.04,-157.48 1155,157.48
3D body "ESQ-102-XX-X-D.step": height 741.18, standoff 216.18, extent 867.84,421.5 1067.84,641.5
3D body "ESQ-102-XX-X-D.step": height 741.18, standoff 216.18, extent 867.84,-641.5 1067.84,-421.5
3D body "CGD1700GB2M-UNA.step": height 1201.97, standoff 384.4, extent -1190,-1291.5 1160,1000

## CGD1700HB2P-UNA_NOHOLE(ALT) [mil] "Wolfpack FM/GM Gate Driver"
pads (8):
  rect 50x125 smd: 1A(917.84,369) 1B(917.84,-694) 2A(917.84,694) 2B(917.84,-369) 3A(1017.84,369) 3B(1017.84,-694) 4A(1017.84,694) 4B(1017.84,-369)
Top Courtyard:
  dashed: 1164.68,-965 1164.68,965 1164.55,968.05 1164.15,971.08 1163.49,974.06 1162.57,976.97 1161.41,979.79 1160,982.5 1158.36,985.08 1156.5,987.5 1154.43,989.75 1152.18,991.81 1149.76,993.67 1147.18,995.31 1144.48,996.72 1141.66,997.89 1138.74,998.81 1135.76,999.47 1132.74,999.87 1129.68,1000 -1150.32,1000 -1153.37,999.87 -1156.39,999.47 -1159.37,998.81 -1162.29,997.89 -1165.11,996.72 -1167.82,995.31 -1170.39,993.67 -1172.81,991.81 -1175.06,989.75 -1177.13,987.5 -1178.99,985.08 -1180.63,982.5 -1182.04,979.79 -1183.2,976.97 -1184.12,974.06 -1184.78,971.08 -1185.18,968.05 -1185.32,965 -1185.32,-965 -1185.18,-968.05 -1184.78,-971.08 -1184.12,-974.06 -1183.2,-976.97 -1182.04,-979.79 -1180.63,-982.5 -1178.99,-985.08 -1177.13,-987.5 -1175.06,-989.75 -1172.81,-991.81 -1170.39,-993.67 -1167.82,-995.31 -1165.11,-996.72 -1162.29,-997.89 -1159.37,-998.81 -1156.39,-999.47 -1153.37,-999.87 -1150.32,-1000 1129.68,-1000 1132.74,-999.87 1135.76,-999.47 1138.74,-998.81 1141.66,-997.89 1144.48,-996.72 1147.18,-995.31 1149.76,-993.67 1152.18,-991.81 1154.43,-989.75 1156.5,-987.5 1158.36,-985.08 1160,-982.5 1161.41,-979.79 1162.57,-976.97 1163.49,-974.06 1164.15,-971.08 1164.55,-968.05
Top 3D Body:
  region: 1164.68,-965 1164.68,965 1164.55,968.05 1164.15,971.08 1163.49,974.06 1162.57,976.97 1161.41,979.79 1160,982.5 1158.36,985.08 1156.5,987.5 1154.43,989.75 1152.18,991.81 1149.76,993.67 1147.18,995.31 1144.48,996.72 1141.66,997.89 1138.74,998.81 1135.76,999.47 1132.74,999.87 1129.68,1000 -1150.32,1000 -1153.37,999.87 -1156.39,999.47 -1159.37,998.81 -1162.29,997.89 -1165.11,996.72 -1167.82,995.31 -1170.39,993.67 -1172.81,991.81 -1175.06,989.75 -1177.13,987.5 -1178.99,985.08 -1180.63,982.5 -1182.04,979.79 -1183.2,976.97 -1184.12,974.06 -1184.78,971.08 -1185.18,968.05 -1185.32,965 -1185.32,-965 -1185.18,-968.05 -1184.78,-971.08 -1184.12,-974.06 -1183.2,-976.97 -1182.04,-979.79 -1180.63,-982.5 -1178.99,-985.08 -1177.13,-987.5 -1175.06,-989.75 -1172.81,-991.81 -1170.39,-993.67 -1167.82,-995.31 -1165.11,-996.72 -1162.29,-997.89 -1159.37,-998.81 -1156.39,-999.47 -1153.37,-999.87 -1150.32,-1000 1129.68,-1000 1132.74,-999.87 1135.76,-999.47 1138.74,-998.81 1141.66,-997.89 1144.48,-996.72 1147.18,-995.31 1149.76,-993.67 1152.18,-991.81 1154.43,-989.75 1156.5,-987.5 1158.36,-985.08 1160,-982.5 1161.41,-979.79 1162.57,-976.97 1163.49,-974.06 1164.15,-971.08 1164.55,-968.05
Mechanical 12:
  lines w1: 867.84,-631.5 867.84,-431.5 1067.84,-431.5 1067.84,-631.5 867.84,-631.5 ; 867.84,431.5 867.84,631.5 1067.84,631.5 1067.84,431.5 867.84,431.5 ; 917.83,-611.5 cw(c917.83,-581.5) 917.83,-551.49 cw(c917.83,-581.5) 917.83,-611.5 ; 917.83,-511.5 cw(c917.83,-481.5) 917.83,-451.49 cw(c917.83,-481.5) 917.83,-511.5 ; 917.83,451.49 cw(c917.83,481.5) 917.83,511.5 cw(c917.83,481.5) 917.83,451.49 ; 917.83,551.49 cw(c917.83,581.5) 917.83,611.5 cw(c917.83,581.5) 917.83,551.49 ; 1017.83,-611.5 cw(c1017.83,-581.5) 1017.83,-551.49 cw(c1017.83,-581.5) 1017.83,-611.5 ; 1017.83,-511.5 cw(c1017.83,-481.5) 1017.83,-451.49 cw(c1017.83,-481.5) 1017.83,-511.5 ; 1017.83,451.49 cw(c1017.83,481.5) 1017.83,511.5 cw(c1017.83,481.5) 1017.83,451.49 ; 1017.83,551.49 cw(c1017.83,581.5) 1017.83,611.5 cw(c1017.83,581.5) 1017.83,551.49
Mechanical 13:
  lines w1: 892.84,-619 1042.84,-619 1042.84,-444 892.84,-444 892.84,-619 ; 892.84,444 1042.84,444 1042.84,619 892.84,619 892.84,444
Mechanical 15:
  text "4" at 997.84,-744 h25
  text "42" at 877.84,-744 h25
  text "2" at 997.84,319 h25
  text "22" at 877.84,319 h25
  text "3" at 997.84,-419 h25
  text "32" at 877.84,-419 h25
  text "1" at 997.84,644 h25
  text "12" at 877.84,644 h25
Top Assembly:
  circle w1: c-1017.84,832.52 r87.5
  circle w1: c-1017.84,-832.52 r87.5
  lines w1: -1185.32,-965 ccw(c-1150.32,-965) -1150.32,-1000 1129.68,-1000 ccw(c1129.68,-965) 1164.68,-965 1164.68,965 ccw(c1129.68,965) 1129.68,1000 -1150.32,1000 ccw(c-1150.32,965) -1185.32,965 -1185.32,-965 ; -1175.32,-550 -815.32,-550 -815.32,550 -1175.32,550 -1175.32,-550 ; -1175.32,-95 -1135.32,-95 -1135.32,95 -1175.32,95 -1175.32,-95 ; -1045.32,-370 cw(c-1045.32,-350) -1045.32,-330 cw(c-1045.32,-350) -1045.32,-370 ; -1045.32,-270 cw(c-1045.32,-250) -1045.32,-230 cw(c-1045.32,-250) -1045.32,-270 ; -1045.32,-170 cw(c-1045.32,-150) -1045.32,-130 cw(c-1045.32,-150) -1045.32,-170 ; -1045.32,-70 cw(c-1045.32,-50) -1045.32,-30 cw(c-1045.32,-50) -1045.32,-70 ; -1045.32,30 cw(c-1045.32,50) -1045.32,70 cw(c-1045.32,50) -1045.32,30 ; -1045.32,130 cw(c-1045.32,150) -1045.32,170 cw(c-1045.32,150) -1045.32,130 ; -1045.32,230 cw(c-1045.32,250) -1045.32,270 cw(c-1045.32,250) -1045.32,230 ; -1045.32,330 cw(c-1045.32,350) -1045.32,370 cw(c-1045.32,350) -1045.32,330 ; -945.32,-370 cw(c-945.32,-350) -945.32,-330 cw(c-945.32,-350) -945.32,-370 ; -945.32,-270 cw(c-945.32,-250) -945.32,-230 cw(c-945.32,-250) -945.32,-270 ; -945.32,-170 cw(c-945.32,-150) -945.32,-130 cw(c-945.32,-150) -945.32,-170 ; -945.32,-70 cw(c-945.32,-50) -945.32,-30 cw(c-945.32,-50) -945.32,-70 ; -945.32,30 cw(c-945.32,50) -945.32,70 cw(c-945.32,50) -945.32,30 ; -945.32,130 cw(c-945.32,150) -945.32,170 cw(c-945.32,150) -945.32,130 ; -945.32,230 cw(c-945.32,250) -945.32,270 cw(c-945.32,250) -945.32,230 ; -945.32,330 cw(c-945.32,350) -945.32,370 cw(c-945.32,350) -945.32,330 ; 867.84,-631.5 1067.84,-631.5 1067.84,-431.5 867.84,-431.5 867.84,-631.5 ; 867.84,431.5 1067.84,431.5 1067.84,631.5 867.84,631.5 867.84,431.5
  text "HS" at 1155.18,470.79 h75
  text "LS" at 1155.18,-589.21 h75
  text "S" at 1002.18,247 h75
  text "G" at 1002.18,772 h75
  text "G" at 1002.18,-303 h75
  text "S" at 1002.18,-828 h75
Multi-Layer keep-out:
  region: -1017.84,-675.04 -1031.56,-675.64 -1045.18,-677.43 -1058.59,-680.41 -1071.7,-684.54 -1084.39,-689.79 -1096.58,-696.14 -1108.16,-703.52 -1119.06,-711.88 -1129.19,-721.16 -1138.47,-731.29 -1146.84,-742.19 -1154.22,-753.78 -1160.56,-765.97 -1165.82,-778.66 -1169.95,-791.76 -1172.92,-805.17 -1174.72,-818.79 -1175.32,-832.52 -1174.72,-846.25 -1172.92,-859.87 -1169.95,-873.28 -1165.82,-886.38 -1160.56,-899.07 -1154.22,-911.26 -1146.84,-922.85 -1138.47,-933.75 -1129.19,-943.88 -1119.06,-953.16 -1108.16,-961.52 -1096.58,-968.9 -1084.39,-975.25 -1071.7,-980.5 -1058.59,-984.63 -1045.18,-987.61 -1031.56,-989.4 -1017.84,-990 -1004.11,-989.4 -990.49,-987.61 -977.08,-984.63 -963.97,-980.5 -951.28,-975.25 -939.1,-968.9 -927.51,-961.52 -916.61,-953.16 -906.48,-943.88 -897.2,-933.75 -888.83,-922.85 -881.45,-911.26 -875.11,-899.07 -869.85,-886.38 -865.72,-873.28 -862.75,-859.87 -860.95,-846.25 -860.36,-832.52 -860.95,-818.79 -862.75,-805.17 -865.72,-791.76 -869.85,-778.66 -875.11,-765.97 -881.45,-753.78 -888.83,-742.19 -897.2,-731.29 -906.48,-721.16 -916.61,-711.88 -927.51,-703.52 -939.1,-696.14 -951.28,-689.79 -963.97,-684.54 -977.08,-680.41 -990.49,-677.43 -1004.11,-675.64
  region: -1017.84,990 -1031.56,989.4 -1045.18,987.61 -1058.59,984.63 -1071.7,980.5 -1084.39,975.25 -1096.58,968.9 -1108.16,961.52 -1119.06,953.16 -1129.19,943.88 -1138.47,933.75 -1146.84,922.85 -1154.22,911.26 -1160.56,899.07 -1165.82,886.38 -1169.95,873.28 -1172.92,859.87 -1174.72,846.25 -1175.32,832.52 -1174.72,818.79 -1172.92,805.17 -1169.95,791.76 -1165.82,778.66 -1160.56,765.97 -1154.22,753.78 -1146.84,742.19 -1138.47,731.29 -1129.19,721.16 -1119.06,711.88 -1108.16,703.52 -1096.58,696.14 -1084.39,689.79 -1071.7,684.54 -1058.59,680.41 -1045.18,677.43 -1031.56,675.64 -1017.84,675.04 -1004.11,675.64 -990.49,677.43 -977.08,680.41 -963.97,684.54 -951.28,689.79 -939.1,696.14 -927.51,703.52 -916.61,711.88 -906.48,721.16 -897.2,731.29 -888.83,742.19 -881.45,753.78 -875.11,765.97 -869.85,778.66 -865.72,791.76 -862.75,805.17 -860.95,818.79 -860.36,832.52 -860.95,846.25 -862.75,859.87 -865.72,873.28 -869.85,886.38 -875.11,899.07 -881.45,911.26 -888.83,922.85 -897.2,933.75 -906.48,943.88 -916.61,953.16 -927.51,961.52 -939.1,968.9 -951.28,975.25 -963.97,980.5 -977.08,984.63 -990.49,987.61 -1004.11,989.4
Mechanical 17:
  lines w1: -1185.32,-965 ccw(c-1150.32,-965) -1150.32,-1000 1129.68,-1000 ccw(c1129.68,-965) 1164.68,-965 1164.68,965 ccw(c1129.68,965) 1129.68,1000 -1150.32,1000 ccw(c-1150.32,965) -1185.32,965 -1185.32,-965
3D body "CGD1700HB2M-UNA STEP.STEP": height 1020.55, standoff 158.13, extent -1185,-1237 1165,1000
3D body "TSM-102-01-SM-DV.step": height 390, standoff 0, extent 870,-681.5 1070,-378.5
3D body "TSM-102-01-SM-DV.step": height 390, standoff 0, extent 865,378.5 1065,681.5
3D body "95783A015_Nylon 6-6 Male-Female Threaded Hex Standoff.STEP": height 846.46, standoff 0, extent -1135.95,-965.19 -899.72,-699.85
3D body "95783A015_Nylon 6-6 Male-Female Threaded Hex Standoff.STEP": height 846.46, standoff 0, extent -1135.95,699.85 -899.72,965.19

## FP-39-30-1062-MFG [mm]
pads (8):
  rect 2.75x2.75 hole 1.8 paste-2539.97 mask+0: 1(4.2,7.5)
  round 2.75 hole 1.8 paste-2539.97 mask+0: 2(0,7.5) 3(-4.2,7.5) 4(4.2,13) 5(0,13) 6(-4.2,13)
  round 3 hole 3 unplated paste-2539.97 mask+0: ""(-4.2,0.2) ""(4.2,0.2)
Top Overlay:
  circle w0.25: c7.69,7.5 r0.125
  lines w0.2: -5.95,6.59 -7.09,6.59 -7.09,-6.59 7.09,-6.59 7.09,6.59 5.95,6.59
Top Courtyard:
  lines w0.2: -7.19,-6.69 -7.19,14.475 7.19,14.475 7.19,-6.69 -7.19,-6.69
Top 3D Body:
  lines w0.2: -7.09,-6.59 -7.09,6.59 7.09,6.59 7.09,-6.59 -7.09,-6.59
Top Component Center:
  lines w0.1: -0.5,0 0.5,0 ; 0,-0.5 0,0.5
Top Assembly:
  lines w0.2: -7.19,-6.69 -7.19,14.475 7.19,14.475 7.19,-6.69 -7.19,-6.69
  text ".Designator" at 0,4.08 h1
3D body "Conn_Molex_39-30-1062_eec.STEP": height 0.25, standoff 0, extent -7.19,-6.69 7.19,14.475

## FP-CRGP2512-IPC_A [mm]
pads (2):
  rect 1.358x3.506 smd paste+0 mask+0: 1(-3.102,0) 2(3.102,0)
Top Overlay:
  lines w0.2: -2.123,-1.753 2.123,-1.753 ; -2.123,1.753 2.123,1.753
Mechanical 5:
  lines w0.2: -4.281,-2.253 -4.281,2.253 4.281,2.253 4.281,-2.253 -4.281,-2.253
  text ".Designator" at 0,0.188 h1
Mechanical 13:
  lines w0.2: -3.175,-1.6 -3.175,1.6 3.175,1.6 3.175,-1.6 -3.175,-1.6
Mechanical 15:
  lines w0.2: -4.281,-2.253 -4.281,2.253 4.281,2.253 4.281,-2.253 -4.281,-2.253
Top Assembly:
  lines w0.1: -0.5,0 0.5,0 ; 0,-0.5 0,0.5
3D body "Res_TE_CRGP2512F47R_eec.STEP": height 0.25, standoff 0, extent -4.281,-2.253 4.281,2.253

## FP-CRGP2512-IPC_B [mm]
pads (2):
  rect 1.158x3.406 smd paste+0 mask+0: 1(-3.002,0) 2(3.002,0)
Top Overlay:
  lines w0.2: -2.123,-1.703 2.123,-1.703 ; -2.123,1.703 2.123,1.703
Mechanical 5:
  lines w0.2: -3.831,-1.953 -3.831,1.953 3.831,1.953 3.831,-1.953 -3.831,-1.953
  text ".Designator" at 0,0.188 h1
Mechanical 13:
  lines w0.2: -3.175,-1.6 -3.175,1.6 3.175,1.6 3.175,-1.6 -3.175,-1.6
Mechanical 15:
  lines w0.2: -3.831,-1.953 -3.831,1.953 3.831,1.953 3.831,-1.953 -3.831,-1.953
Top Assembly:
  lines w0.1: -0.5,0 0.5,0 ; 0,-0.5 0,0.5
3D body "Res_TE_CRGP2512F47R_eec.STEP": height 0.25, standoff 0, extent -3.831,-1.953 3.831,1.953

## FP-CRGP2512-IPC_C [mm]
pads (2):
  rect 0.958x3.306 smd paste+0 mask+0: 1(-2.902,0) 2(2.902,0)
Top Overlay:
  lines w0.2: -2.123,-1.7 2.123,-1.7 ; -2.123,1.7 2.123,1.7
Mechanical 5:
  lines w0.2: -3.481,-1.8 -3.481,1.8 3.481,1.8 3.481,-1.8 -3.481,-1.8
  text ".Designator" at 0,0.188 h1
Mechanical 13:
  lines w0.2: -3.175,-1.6 -3.175,1.6 3.175,1.6 3.175,-1.6 -3.175,-1.6
Mechanical 15:
  lines w0.2: -3.481,-1.8 -3.481,1.8 3.481,1.8 3.481,-1.8 -3.481,-1.8
Top Assembly:
  lines w0.1: -0.5,0 0.5,0 ; 0,-0.5 0,0.5
3D body "Res_TE_CRGP2512F47R_eec.STEP": height 0.25, standoff 0, extent -3.481,-1.8 3.481,1.8

## FP-RMCF2512-IPC_A [mm]
pads (2):
  rect 1.704x3.555 smd paste+0 mask+0: 1(-2.951,0) 2(2.951,0)
Top Overlay:
  lines w0.2: -1.799,-1.777 1.799,-1.777 ; -1.799,1.777 1.799,1.777
Top Courtyard:
  lines w0.2: -4.303,-2.277 4.303,-2.277 4.303,2.277 -4.303,2.277 -4.303,-2.277
Top 3D Body:
  lines w0.2: -3.15,-1.6 3.15,-1.6 3.15,1.6 -3.15,1.6 -3.15,-1.6
Top Component Center:
  lines w0.1: -0.5,0 0.5,0 ; 0,-0.5 0,0.5
Top Assembly:
  lines w0.2: -4.303,-2.277 4.303,-2.277 4.303,2.277 -4.303,2.277 -4.303,-2.277
  text ".Designator" at 0,0.188 h1
3D body "Res_Stackpole_RMCF2512FT10M0_eec.STEP": height 0.25, standoff 0, extent -4.303,-2.277 4.303,2.277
